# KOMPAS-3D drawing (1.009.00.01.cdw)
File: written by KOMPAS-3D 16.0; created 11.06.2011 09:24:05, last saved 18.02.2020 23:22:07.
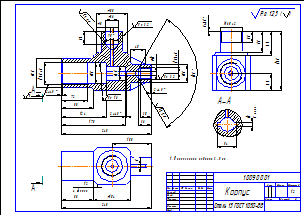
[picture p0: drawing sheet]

Sheet 1: A3, landscape

Title block, sheet 1: name: Корпус; designation: 1.009.00.01; material: Сталь 15 ГОСТ 1050-88; scale: 1:2; sheets: 1; sheet format: A3; stored path: C:\Users\Catonok\Desktop\Корпус1.cdw

Views: Вид 1
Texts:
  Catonok
  Ra 3,2
  Ra 6,3
  Ra 1,6
  Неуказанные радиусы 3...5 мм.
  Ra 12,5
  Ra 12,5 ( )
  Без боковой рамки
  Лит-Масса-Масштаб
  Материал-Предприятие
  Масштаб
  Изм.
  Лист
  № докум.
  Подп.
  Дата
  Лит.
  Разраб.
  Пров.
  Т.контр.
  Листов
  Н.контр.
  Утв.
  Изменение
  Номер документа
  Подпись
  Обозначение документа
  Наименование изделия
  Масса изделия по ГОСТ 2.109-73
  Порядковый номер листа
  Общее количество листов в документе
  Характер работы, выполненной лицом, подписавшим документ
  Наименование или индекс предприятия, выпускающего документ
Dimensions and other numbers on the sheet: 248; 80; 60; 72; 88; 104; 12; 4 фаски; 50; 165; 32; 59; 67; 2; 58; 40; 124; 178; 36; 30; 10; 8; 34; 120; 108; 46; 54; 2 паза; 1:2; 1; 1.009.00.01; 1.009.00.01-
